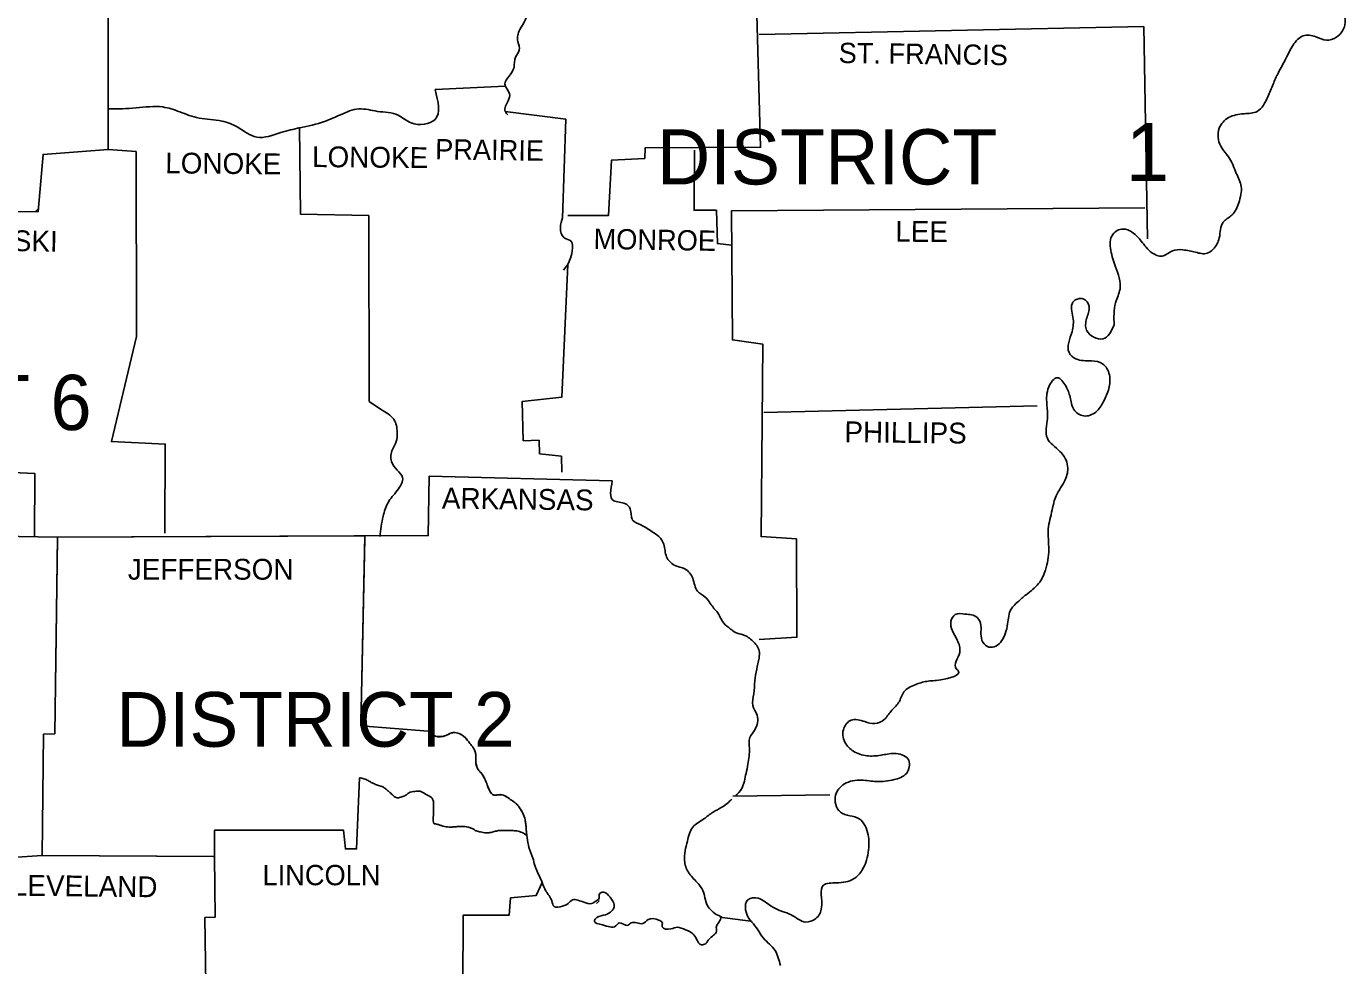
# Model space of a CAD drawing. Extents: x -42408 to 34530, y -43140 to 20491.
# Drawn here: x 9102 to 10466, y 8031 to 9002 of the extents above; entities that cross this region are included whole.
import ezdxf

# ---------------------------------------------------------------- set-up
doc = ezdxf.new("R2010")
doc.units = 0
for name, color, linetype in [('1', 7, 'Continuous'), ('2', 7, 'Continuous'), ('3', 7, 'Continuous'), ('S_MISC_BOUNDARY', 7, 'Continuous')]:
    doc.layers.add(name, color=color, linetype=linetype)

msp = doc.modelspace()

# ---------------------------------------------------------------- linework, layer by layer
at = {"layer": '1'}
msp.add_line((9832.7, 8206), (9932.8, 8207.5), dxfattribs=at)
for points in [[(9153.8, 10018), (9154.8, 9898.8), (9146.3, 9898.3), (9147.8, 9773.6), (9112.7, 9768.6), (9115.7, 9735.1), (9127.7, 9719.6), (9126.7, 9680), (9058.6, 9677.5), (9056.1, 9616.4), (8994.1, 9614.4), (8991, 9540.3), (8994.6, 9534.3), (8996.1, 9416.2), (9103.2, 9409.1), (9101.7, 9145.3), (9186.8, 9142.8), (9186.8, 8874.4), (9119.7, 8869.4), (9114.7, 8810.3), (9002.1, 8809.8)], [(9853.7, 9151.3), (9861.2, 8876.9), (9742.1, 8876.4), (9741.6, 8865.4), (9707, 8863.4), (9704, 8806.3), (9661.9, 8806.3)], [(9859.7, 8993.6), (10257.2, 9001.6)], [(10257.2, 9001.6), (10261.2, 8782.3)], [(9524.8, 8936.5), (9597.4, 8940)], [(9597.4, 8914), (9659.9, 8906), (9656.4, 8803.8)], [(9384.6, 8897.5), (9385.6, 8807.8), (9456.2, 8806.3), (9456.7, 8614.1)], [(9186.8, 8874.4), (9215.8, 8872.4), (9216.3, 8681.2), (9190.3, 8572.5), (9245.9, 8570), (9245.4, 8477.9)], [(9793.1, 8873.9), (9792.6, 8811.8), (9815.6, 8811.8), (9816.7, 8777.3), (9831.2, 8775.8)], [(9112.2, 8810.8), (9114.7, 8813.3)], [(9859.7, 8367.8), (9898.8, 8370.3), (9898.3, 8471.9), (9861.7, 8474.4), (9863.7, 8673.2), (9832.2, 8677.7), (9831.2, 8811.3), (10258.2, 8814.3)], [(9661.9, 8755.8), (9655.9, 8618.6), (9614.9, 8614.1), (9615.9, 8573.5), (9632.4, 8574), (9632.9, 8560), (9655.4, 8557.5), (9655.9, 8541)], [(8800.3, 8749.3), (8856.4, 8745.8), (8854.4, 8683.2), (8920, 8680.7), (8921, 8626.1), (8952, 8623.6), (8952, 8614.1), (8981, 8612.1), (8982, 8577), (9048.1, 8577), (9050.1, 8542.5), (9111.2, 8539.5), (9110.7, 8474.4)], [(9864.7, 8602.6), (10147.1, 8609.6)], [(9708, 8532), (9518.8, 8537), (9517.8, 8475.4), (9134.7, 8473.9)], [(8846.4, 8407.8), (8874.4, 8411.8), (8876.4, 8428.8), (8892.9, 8431.8), (8893.9, 8441.9), (9010.6, 8445.4), (9015.1, 8475.9), (9134.7, 8473.9)], [(9134.7, 8472.9), (9131.7, 8270.6), (9120.2, 8270.1), (9118.7, 8144.5)], [(9452.2, 8472.4), (9448.2, 8278.6), (9517.8, 8273.1)], [(9446.7, 8225.1), (9443.7, 8151.5), (9432.1, 8151.5), (9430.1, 8171), (9297, 8171), (9297, 8143)], [(9118.7, 8144.5), (9045.6, 8139.9)], [(9118.7, 8144.5), (9296, 8143.5)], [(9297, 8143.5), (9297.5, 8080.9), (9286.9, 8080.4), (9289.9, 7872.6)], [(9635.4, 8116.9), (9629.4, 8103.4), (9602.9, 8100.9), (9601.4, 8082.9), (9553.8, 8082.9), (9553.3, 7933.2)], [(9691.5, 8094.9), (9693, 8096.4), (9694.5, 8097.9), (9694.5, 8097.9)]]:
    msp.add_lwpolyline(points, dxfattribs=at)
for points in [[(9660.9, 9209.4), (9658.4, 9192.9), (9648.9, 9188.3), (9637.9, 9177.3), (9635.4, 9167.3), (9626.4, 9163.3), (9617.9, 9152.8), (9612.4, 9138.3), (9612.4, 9123.3), (9615.9, 9106.2), (9628.4, 9101.7), (9634.4, 9091.7), (9633.4, 9081.2), (9645.4, 9074.2), (9647.4, 9068.2), (9645.4, 9061.7), (9639.9, 9043.2), (9640.4, 9030.6), (9639.4, 9025.1), (9625.9, 9021.6), (9617.9, 9008.1), (9612.4, 8998.6), (9610.4, 8986.1), (9611.9, 8977.1), (9607.9, 8970.1), (9606.4, 8959.5), (9601.4, 8950.5), (9596.9, 8942), (9601.9, 8932), (9600.4, 8925), (9597.4, 8914), (9599.9, 8910.5)], [(10444, 9189.3), (10446, 9174.8), (10437.5, 9159.3), (10434.5, 9143.8), (10436, 9128.3), (10420, 9119.8), (10405.9, 9109.7), (10413.9, 9097.7), (10429, 9086.7), (10444, 9078.2), (10453.5, 9069.7), (10456, 9049.2), (10458.5, 9036.1), (10463.5, 9018.1), (10465.5, 9005.6), (10456.5, 8990.6), (10446, 8987.6), (10435, 8991.1), (10422, 8992.1), (10411.4, 8982.1), (10403.9, 8968.1), (10396.4, 8954), (10390.9, 8942), (10385.4, 8929), (10374.4, 8914), (10360.9, 8911.5), (10344.9, 8907.5), (10335.3, 8896.5), (10336.8, 8877.9), (10345.9, 8865.4), (10352.9, 8849.9), (10357.9, 8836.4), (10355.4, 8819.4), (10348.4, 8806.8), (10339.3, 8799.3), (10335.3, 8783.3), (10328.8, 8771.3), (10322.8, 8767.3), (10310.8, 8768.3), (10297.8, 8770.8), (10286.8, 8769.8), (10276.3, 8764.3), (10265.7, 8767.8), (10254.7, 8779.8), (10245.7, 8788.8), (10235.7, 8792.3), (10225.2, 8786.8), (10223.2, 8770.3), (10228.2, 8753.3), (10232.7, 8730.2), (10228.2, 8716.2), (10226.7, 8693.2)], [(9187.8, 8916.5), (9215.8, 8917.5), (9243.4, 8918.5), (9260.9, 8913.5), (9280.9, 8907), (9304.5, 8904), (9321, 8897.5), (9340.5, 8887.4), (9365.5, 8892), (9385.1, 8897), (9410.6, 8903.5), (9427.1, 8910.5), (9446.2, 8916.5), (9465.2, 8914), (9486.7, 8910), (9500.2, 8902), (9524.8, 8905.5), (9524.8, 8936.5)], [(9656.4, 8803.8), (9654.4, 8793.8), (9658.4, 8783.3), (9665.4, 8779.8), (9666.5, 8769.8), (9663.9, 8759.8), (9661.9, 8755.8), (9657.4, 8749.8)], [(10226.7, 8693.2), (10215.2, 8678.7), (10198.2, 8687.7), (10198.2, 8699.7), (10200.7, 8712.2), (10194.7, 8720.2), (10184.1, 8716.7), (10184.1, 8701.2), (10183.1, 8686.2), (10180.1, 8664.6), (10187.1, 8658.1), (10203.2, 8656.1), (10214.7, 8653.1), (10221.7, 8641.6), (10221.2, 8627.6), (10215.7, 8614.1), (10207.7, 8603.1), (10195.2, 8599.1), (10185.1, 8605.6), (10181.1, 8618.6), (10176.6, 8630.1), (10168.1, 8638.6), (10159.1, 8629.1), (10157.1, 8611.6), (10157.6, 8596.6), (10157.6, 8576), (10170.6, 8562.5), (10178.6, 8547), (10176.1, 8533), (10166.6, 8516.5), (10162.6, 8501.9), (10158.6, 8482.4), (10159.1, 8460.9), (10155.6, 8439.8), (10148.6, 8425.8), (10135.6, 8414.3), (10127.1, 8406.8), (10120.1, 8399.3), (10116.6, 8384.3), (10114, 8373.8), (10104.5, 8361.2), (10097, 8360.2), (10091, 8365.3), (10089, 8373.8), (10089, 8382.3), (10085, 8390.8), (10072.5, 8394.3), (10062.5, 8393.8), (10058, 8386.8), (10064.5, 8367.3), (10067, 8354.7), (10063.5, 8337.7), (10065.5, 8335.7), (10047.5, 8326.2), (10032.9, 8324.7), (10020.9, 8321.2), (10009.4, 8313.7), (10003.9, 8302.7), (9995.9, 8293.7), (9988.9, 8285.1), (9979.4, 8281.1), (9968.9, 8283.1), (9954.8, 8284.6), (9946.8, 8274.6), (9949.3, 8260.1), (9958.8, 8251.6), (9972.9, 8247.6), (9987.4, 8248.6), (10001.4, 8250.1), (10014.4, 8243.1), (10011.9, 8229.6), (9999.4, 8223.1), (9980.9, 8221.1), (9965.8, 8222.6), (9947.8, 8218.6), (9938.8, 8207), (9943.8, 8189.5), (9963.3, 8182.5), (9972.4, 8166), (9972.9, 8150.5), (9966.4, 8129.9), (9957.3, 8120.4), (9939.8, 8116.4), (9926.3, 8113.9), (9924.3, 8090.9), (9918.3, 8079.4), (9907.8, 8075.9), (9892.8, 8083.4), (9883.7, 8086.9), (9872.7, 8091.9), (9858.7, 8100.4), (9848.2, 8098.9), (9851.2, 8076.9), (9852.2, 8075.9), (9864.2, 8059.3), (9876.2, 8046.3), (9881.7, 8030.8)], [(9456.7, 8614.1), (9469.2, 8605.6), (9482.2, 8595.6), (9485.7, 8582), (9484.7, 8572.5), (9480.7, 8564.5), (9479.7, 8552), (9485.7, 8543), (9491.2, 8535.5), (9485.7, 8522), (9476.2, 8509.4), (9471.2, 8495.4), (9467.7, 8474.4)], [(9708, 8532), (9709.5, 8511.4), (9721.5, 8508.4), (9726.5, 8502.9), (9729, 8491.4), (9737.5, 8486.4), (9749.1, 8479.4), (9756.1, 8474.4), (9761.1, 8466.4), (9764.1, 8453.4), (9772.1, 8444.9), (9783.1, 8440.9), (9791.1, 8431.3), (9796.1, 8417.8), (9804.1, 8411.8), (9812.1, 8401.3), (9816.1, 8396.8), (9823.2, 8384.8), (9830.2, 8378.8), (9835.2, 8375.3), (9843.2, 8372.8), (9853.2, 8366.3), (9859.7, 8356.2), (9859.7, 8348.7), (9857.2, 8337.2), (9855.2, 8325.2), (9854.2, 8311.7), (9853.2, 8299.7), (9857.7, 8289.6), (9855.2, 8274.6), (9850.2, 8266.6), (9849.7, 8255.6), (9848.2, 8239.1), (9846.2, 8229.6), (9841.7, 8214), (9835.2, 8206)], [(9517.8, 8273.1), (9525.3, 8268.1), (9535.8, 8268.6), (9542.8, 8271.6), (9548.3, 8271.1), (9555.8, 8266.6), (9560.8, 8260.6), (9564.3, 8256.1), (9566.8, 8249.1), (9566.8, 8242.6), (9569.3, 8233.6), (9572.3, 8230.1), (9576.3, 8223.6), (9578.8, 8217.6), (9580.3, 8213.5), (9585.8, 8207), (9590.8, 8207.5), (9595.4, 8207), (9601.4, 8203.5), (9610.4, 8196.5), (9611.9, 8194.5), (9617.9, 8181.5), (9618.9, 8173.5), (9619.9, 8163), (9621.9, 8153), (9625.9, 8142), (9627.9, 8134.4), (9632.4, 8123.9), (9635.4, 8116.9), (9639.4, 8107.9), (9645.4, 8097.9), (9647.9, 8091.9), (9656.4, 8092.4), (9662.4, 8094.9), (9667, 8098.9), (9672.5, 8098.4), (9678.5, 8096.4), (9686.5, 8094.9), (9691.5, 8097.9), (9694, 8099.9), (9694.5, 8104.4), (9699, 8106.9), (9704, 8103.4), (9709.5, 8095.4), (9709.5, 8090.4), (9707.5, 8087.4), (9701, 8083.4), (9692, 8080.4), (9689.5, 8076.9), (9698, 8072.9), (9711.5, 8071.9), (9715, 8074.9), (9724, 8072.4), (9727.5, 8074.9), (9739.5, 8074.4), (9745.1, 8078.4), (9756.1, 8077.9), (9759.6, 8075.4), (9759.6, 8070.9), (9768.6, 8068.9), (9775.1, 8070.4), (9783.6, 8067.9), (9791.1, 8063.8), (9795.1, 8058.3), (9800.1, 8052.3), (9804.6, 8053.8), (9808.1, 8058.3), (9815.6, 8066.4), (9815.6, 8071.4), (9817.7, 8074.9), (9820.2, 8079.9)], [(9831.7, 8203), (9821.2, 8194.5), (9812.1, 8189.5), (9802.6, 8182.5), (9791.1, 8174), (9785.6, 8159.5), (9782.6, 8139.4), (9786.6, 8127.4), (9795.6, 8116.9), (9801.6, 8108.4), (9806.1, 8093.4), (9817.2, 8082.9), (9820.7, 8081.4)]]:
    msp.add_spline(points, degree=3, dxfattribs=at)
at = {"layer": '3'}
msp.add_line((9819.2, 8080.9), (9850.7, 8076.9), dxfattribs=at)
at = {"layer": 'S_MISC_BOUNDARY'}
for p, q in [((9452.2, 8475.1), (9134.7, 8473.9)), ((9118.7, 8144.5), (9297, 8143.5))]:
    msp.add_line(p, q, dxfattribs=at)
for points in [[(9134.7, 8473.9), (9131.7, 8270.6), (9120.2, 8270.1), (9118.7, 8144.5)], [(9517.8, 8273.1), (9448.2, 8278.6), (9452.2, 8475.1)], [(9297, 8143.5), (9297, 8171), (9430.1, 8171), (9432.1, 8151.5), (9443.7, 8151.5), (9446.7, 8225.1)]]:
    msp.add_lwpolyline(points, dxfattribs=at)
for points in [[(9573.8, 8228), (9572.3, 8230.1), (9571.6, 8231), (9570.8, 8231.8), (9570, 8232.6), (9569.3, 8233.6), (9567.6, 8238), (9566.8, 8242.6), (9566.8, 8244.2), (9566.8, 8245.8), (9566.9, 8247.5), (9566.8, 8249.1), (9566.5, 8250.9), (9566, 8252.7), (9564.3, 8256.1), (9560.8, 8260.6), (9555.8, 8266.6), (9552.4, 8269.3), (9550.4, 8270.3), (9548.3, 8271.1), (9545.6, 8271.7), (9544.2, 8271.8), (9542.8, 8271.6), (9541, 8271.1), (9539.3, 8270.2), (9537.5, 8269.3), (9535.8, 8268.6), (9530.5, 8267.7), (9527.9, 8267.6), (9525.3, 8268.1), (9523.2, 8269), (9521.2, 8270.1), (9517.8, 8273.1)], [(9446.7, 8225.1), (9449, 8224.6), (9451.3, 8223.9), (9455.7, 8222.1), (9457.3, 8221.2), (9458.9, 8220.3), (9460.5, 8219.4), (9462.2, 8218.6), (9464.3, 8217.8), (9466.5, 8217.1), (9468.6, 8216.5), (9470.7, 8215.6), (9473.5, 8213.6), (9476.2, 8211.5), (9478.1, 8209.9), (9479.9, 8208.2), (9481.8, 8206.5), (9482.7, 8205.8), (9483.7, 8205), (9485.8, 8204.3), (9488.1, 8204.5), (9490.5, 8205.2), (9492.7, 8206), (9494.4, 8207), (9495.9, 8208.1), (9497.5, 8209.2), (9499.2, 8210), (9505.7, 8211), (9509.3, 8211)], [(9619.7, 8165.3), (9618.9, 8173.5), (9618.5, 8177.5), (9618.2, 8179.5), (9617.9, 8181.5), (9615.5, 8188.2), (9613.8, 8191.4), (9611.9, 8194.5), (9610.4, 8196.5), (9609.4, 8197.5), (9608.3, 8198.5), (9606.1, 8200.3), (9601.4, 8203.5), (9598.5, 8205.5), (9597, 8206.3), (9596.2, 8206.7), (9595.4, 8207), (9593.1, 8207.5), (9590.8, 8207.5), (9589.6, 8207.4), (9588.3, 8207.1), (9587.1, 8206.9), (9585.8, 8207), (9584.8, 8207.5), (9583.9, 8208.1), (9582.4, 8209.7), (9581.8, 8210.6), (9581.3, 8211.6), (9580.3, 8213.5), (9578.8, 8217.6), (9576.3, 8223.6), (9574.5, 8226.9), (9573.8, 8228)], [(9509.3, 8211), (9510.7, 8210.5), (9516.2, 8207.5), (9517.1, 8207.1), (9519.5, 8205.7), (9521, 8204.6), (9521.7, 8203.9), (9522, 8203.5), (9522.3, 8203), (9523.2, 8199.8), (9523.3, 8198.2), (9523.3, 8196.5), (9523.3, 8189), (9523.3, 8178.5), (9523.6, 8177.8), (9524.5, 8177.4), (9526.3, 8177.1), (9526.8, 8177), (9529.9, 8176), (9533, 8175.1), (9539.3, 8174), (9541.4, 8174), (9543.5, 8174.2), (9545.7, 8174.4), (9547.8, 8174.5), (9551.8, 8174.6), (9552.3, 8174.6)], [(9552.3, 8174.6), (9555.8, 8174.5), (9559.1, 8174), (9560.7, 8173.5), (9562.3, 8173), (9563.7, 8172.3), (9565.1, 8171.5), (9566.4, 8170.6), (9567.8, 8170), (9571.8, 8169), (9577.8, 8168), (9582.8, 8168.5), (9585, 8169), (9587.1, 8169.7), (9589.2, 8170.2), (9591.3, 8170.5), (9596.4, 8170.5), (9604.4, 8170.5), (9606.9, 8170.3), (9608.1, 8170.2), (9609.4, 8170), (9614.8, 8168.4), (9619.7, 8165.3)]]:
    msp.add_spline(points, degree=3, dxfattribs=at)

# ---------------------------------------------------------------- texts
at = {"layer": '1'}
msp.add_text('1', height=60.1, dxfattribs=at).set_placement((10238.7, 8841.9))
at = {"layer": '2'}
for s, height, rotation, p in [('ST. FRANCIS', 21.022, 359.2216, (9941.8, 8964)), ('LONOKE', 21.53, 359.4974, (9397.6, 8856.4)), ('PRAIRIE', 21.03, 359.2116, (9524.8, 8864.4)), ('LONOKE', 21.53, 359.4974, (9245.9, 8849.9)), ('LEE', 21.53, 359.4327, (10000.4, 8779.3)), ('PULASKI', 21.53, 359.053, (9013.1, 8770.8)), ('MONROE', 21.02, 359.0331, (9688.5, 8771.8)), ('PHILLIPS', 21.52, 359.3179, (9947.8, 8572)), ('ARKANSAS', 21.52, 359.2678, (9531.8, 8503.4)), ('CLEVELAND', 21.53, 359.3377, (9066.6, 8103.4))]:
    msp.add_text(s, height=height, rotation=rotation, dxfattribs=at).set_placement(p)
for s, height, p in [('JEFFERSON', 21.53, (9207.3, 8429.8)), ('LINCOLN', 21.03, (9346.5, 8113.9))]:
    msp.add_text(s, height=height, dxfattribs=at).set_placement(p)
at = {"layer": '3'}
for s, height, p in [('DISTRICT', 57.08, (9754.1, 8838.4)), ('DISTRICT 6', 57.08, (8754.2, 8584.5)), ('DISTRICT 2', 56.57, (9195.3, 8257.1))]:
    msp.add_text(s, height=height, dxfattribs=at).set_placement(p)

doc.saveas('drawing.dxf')
